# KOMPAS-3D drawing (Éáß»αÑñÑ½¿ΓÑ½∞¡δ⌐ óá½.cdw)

Referenced files in D:\Мои\Диплом\: Чертеж.cdw
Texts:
  ДП 190604.09.044.16 ПЗ
  Распределительный вал
  Ильдар
  Распред вал
  Номе
  Текст на чертеже
  Размерные надписи
  Шероховатость
  Линия-выноска #1
  Линия-выноска #2
  Линия-выноска #3
  Отклонения формы и база
  Заголовок таблицы
  Ячейка таблицы
  Стрелка вида
  Обозначение изменения
  Фигурная скобка
  Номер узла
  Марка координационной оси
  Выносная надпись
  Обозначение узла
  Марка/позиционное обозначение с линией-выноской
  Марка/позиционное обозначение на линии
  Марка/позиционное обозначение без линии-выноски
  max
  Rz1.6
  Rz0.8
  Rz6.3
  Rz12.5
  Rz3.2
  Rz100
  1. Твердость неотбеливающей части и шеек НВ 187-300
  2. Не допускается попадание стружки и грязи в масленные каналы
  3. Механические свойства материала и тех. требования на отливку по ТЦ 036
  4.Неуказанные тех. требования на отливку по ГОСТ 1412-79
  5 Неуказанные шероховатости кулачков и шеек 0,32 , 0,4
  Казаев И.С.
  Зайцев В.М.
  Сталь 45 ГОСТ 1050-88
  ДП 190604.09.044.16 ПЗ-
  УАТ гр.АТ-44
  Рецензет
  Закиров М.М.
Dimensions and other numbers on the sheet: 7; 8; 10; 15; 36; 45; 12; 17; 16; 32; 34; 38; 46; 69; 120; 4; 1,5; 12,5; 37,5; 61,5; 80; 141,5; 165,5; 207,5; 245,5; 269,5; 293,5; 361; 385; 398; 435; 5; 15,25; 11; 14; 4,5; 70; 105; 189; 222; 258; 310; 338; 455; 461; 0,22; 35; 0,02; 2,5; 4отв.; 4h0,5; 0,5; 3; 1; 1:1; 0; 2; 6; 9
